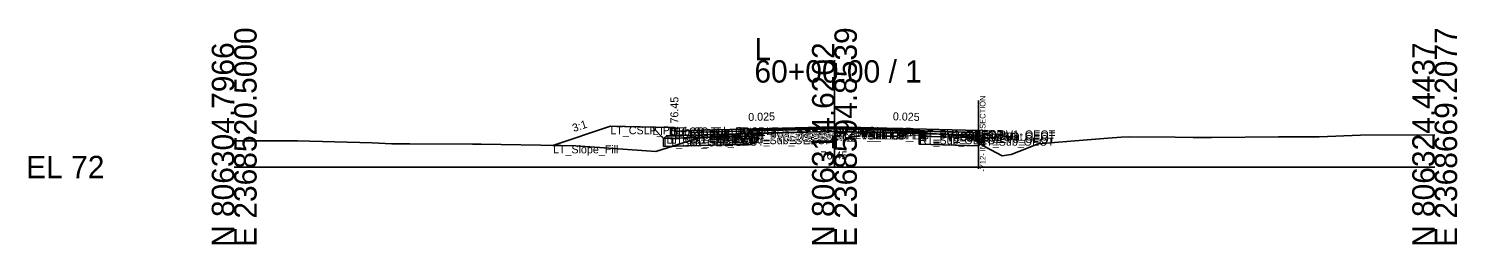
# Model space of a CAD drawing. Extents: x -26 to 8153, y -10 to 9520.
# Drawn here: x 4974.3 to 5152.8, y 8990.3 to 9017.3 of the extents above; entities that cross this region are included whole.
import ezdxf

# ---------------------------------------------------------------- set-up
doc = ezdxf.new("R2010")
doc.units = 0
for name, color, linetype in [('Exist CMT Pavement', 7, 'Continuous'), ('Exist Cross Section Cell', 7, 'Continuous'), ('Exist XS Center Line Elevation Label', 7, 'Continuous'), ('Exist XS Ground Line', 7, 'Continuous'), ('Prop CMT Conc Surface', 7, 'Continuous'), ('Prop CMT Concrete Structures', 7, 'Continuous'), ('Prop CMT Pvmt Course 1', 7, 'Continuous'), ('Prop CMT Pvmt Course 1 CG', 7, 'Continuous'), ('Prop CMT Pvmt Course 1 Wedge', 7, 'Continuous'), ('Prop CMT Pvmt Course 2', 7, 'Continuous'), ('Prop CMT Pvmt Course 2 Wedge', 7, 'Continuous'), ('Prop CMT Pvmt Course 3', 7, 'Continuous'), ('Prop CMT Pvmt Course 3 Wedge', 7, 'Continuous'), ('Prop CMT Pvmt Surface', 7, 'Continuous'), ('Prop CMT Pvmt Wedge Surface 1', 7, 'Continuous'), ('Prop CMT Pvmt Wedge Surface 2', 7, 'Continuous'), ('Prop CMT Pvmt Wedge Surface 3', 7, 'Continuous'), ('Prop CMT Shallow Undercut', 7, 'Continuous'), ('Prop CMT Shallow Undercut Boundary', 7, 'Continuous'), ('Prop CMT Shear Line', 7, 'Continuous'), ('Prop CMT Slope Grass', 7, 'Continuous'), ('Prop CMT Subgrade Earthwork', 7, 'Continuous'), ('Prop XS Earthwork Shape', 7, 'Continuous'), ('Prop XS Hydro Elevations', 7, 'Continuous'), ('Prop XS SE Text', 7, 'Continuous'), ('Prop XS Side Slope Text', 7, 'Continuous'), ('Prop XS Subgrade Earthwork', 7, 'Continuous'), ('Scratch_Level_2', 7, 'Continuous'), ('Scratch_Level_6', 7, 'Continuous')]:
    doc.layers.add(name, color=color, linetype=linetype)

msp = doc.modelspace()

# ---------------------------------------------------------------- linework, layer by layer
at = {"layer": 'Exist CMT Pavement'}
for p, q in [((5064.59, 9004.26), (5072.68, 9004.42)), ((5072.68, 9004.42), (5074.68, 9004.46)), ((5074.68, 9004.46), (5075, 9004.45)), ((5075, 9004.45), (5077.04, 9004.41)), ((5077.04, 9004.41), (5085.6, 9004.31))]:
    msp.add_line(p, q, dxfattribs=at)
at = {"layer": 'Exist Cross Section Cell'}
for p, q in [((5075, 9000), (5075, 9013.37)), ((5000, 9000), (5075, 9000)), ((5075, 9000), (5150, 9000))]:
    msp.add_line(p, q, dxfattribs=at)
at = {"layer": 'Exist XS Ground Line'}
for p, q in [((5052.7, 9001.93), (5057.94, 9003.63)), ((5057.94, 9003.63), (5062.69, 9004.08)), ((5062.69, 9004.08), (5064.59, 9004.26)), ((5064.59, 9004.26), (5072.68, 9004.42)), ((5072.68, 9004.42), (5074.68, 9004.46)), ((5074.68, 9004.46), (5075, 9004.45)), ((5075, 9004.45), (5077.04, 9004.41)), ((5077.04, 9004.41), (5085.6, 9004.31)), ((5085.6, 9004.31), (5087.26, 9004.18)), ((5087.26, 9004.18), (5091.74, 9003.84)), ((5091.74, 9003.84), (5093.83, 9002.54)), ((5104.53, 9003.25), (5109.15, 9003.61)), ((5109.15, 9003.61), (5110.81, 9003.75)), ((5110.81, 9003.75), (5111.86, 9003.79)), ((5111.86, 9003.79), (5117.57, 9003.73)), ((5117.57, 9003.73), (5119.84, 9003.69)), ((5119.84, 9003.69), (5122.13, 9003.69)), ((5122.13, 9003.69), (5130.48, 9003.77)), ((5130.48, 9003.77), (5135.56, 9003.79)), ((5135.56, 9003.79), (5140.73, 9003.98)), ((5140.73, 9003.98), (5150, 9004.04)), ((5000, 9003.26), (5002.86, 9003.29)), ((5002.86, 9003.29), (5007.9, 9003.26)), ((5007.9, 9003.26), (5017.22, 9003.01)), ((5017.22, 9003.01), (5019.68, 9002.92)), ((5019.68, 9002.92), (5021.94, 9002.91)), ((5021.94, 9002.91), (5029.77, 9002.86)), ((5029.77, 9002.86), (5030.85, 9002.86)), ((5030.85, 9002.86), (5040.83, 9002.69)), ((5040.83, 9002.69), (5042.69, 9002.65)), ((5042.69, 9002.65), (5052.7, 9001.93)), ((5093.83, 9002.54), (5095.94, 9001.42)), ((5097.1, 9001.59), (5098.04, 9001.96)), ((5098.04, 9001.96), (5100.46, 9002.9)), ((5100.46, 9002.9), (5104.53, 9003.25)), ((5095.94, 9001.42), (5096.8, 9001.52)), ((5096.8, 9001.52), (5097.1, 9001.59))]:
    msp.add_line(p, q, dxfattribs=at)
at = {"layer": 'Prop CMT Conc Surface'}
for points in [[(5055, 9004.45), (5055, 9004.95), (5054.5, 9004.95)], [(5057, 9004.58), (5055, 9004.45)]]:
    msp.add_lwpolyline(points, dxfattribs=at)
at = {"layer": 'Prop CMT Concrete Structures'}
for points in [[(5057, 9004.58), (5055, 9004.45), (5055, 9004.95), (5054.5, 9004.95)], [(5054.5, 9004.95), (5054.5, 9003.93), (5057, 9004)], [(5057, 9004), (5057, 9004.58)]]:
    msp.add_lwpolyline(points, dxfattribs=at)
at = {"layer": 'Prop CMT Pvmt Course 1'}
for points in [[(5075, 9005.03), (5057, 9004.58)], [(5057, 9004.58), (5057, 9004.33)], [(5057, 9004.33), (5064.59, 9004.52)], [(5064.59, 9004.64), (5075, 9004.91)], [(5064.59, 9004.52), (5064.59, 9004.64)], [(5075, 9004.78), (5075, 9005.03)], [(5075, 9005.03), (5093, 9004.58)], [(5075, 9004.78), (5075, 9005.03)], [(5075, 9004.91), (5075, 9004.78), (5075, 9004.78)], [(5085.6, 9004.64), (5075, 9004.91)], [(5075, 9004.91), (5075, 9004.78), (5075, 9004.78)], [(5085.6, 9004.51), (5085.6, 9004.64)], [(5093, 9004.33), (5085.6, 9004.51)], [(5093, 9004.58), (5093, 9004.33)]]:
    msp.add_lwpolyline(points, dxfattribs=at)
at = {"layer": 'Prop CMT Pvmt Course 1 CG'}
for points in [[(5057, 9004), (5054, 9003.92), (5053.66, 9003.58)], [(5053.66, 9003.58), (5057, 9003.67)], [(5057, 9003.67), (5057, 9004)]]:
    msp.add_lwpolyline(points, dxfattribs=at)
at = {"layer": 'Prop CMT Pvmt Course 1 Wedge'}
for points in [[(5075, 9004.91), (5064.59, 9004.64)], [(5075, 9004.91), (5085.6, 9004.64)]]:
    msp.add_lwpolyline(points, dxfattribs=at)
at = {"layer": 'Prop CMT Pvmt Course 2'}
for points in [[(5064.59, 9004.52), (5057, 9004.33)], [(5057, 9004.33), (5057, 9004)], [(5057, 9004), (5064.59, 9004.19)], [(5064.59, 9004.19), (5064.59, 9004.52)], [(5085.6, 9004.18), (5085.6, 9004.51)], [(5085.6, 9004.51), (5093, 9004.33)], [(5093, 9004), (5085.6, 9004.18)], [(5093, 9004.33), (5093, 9004)]]:
    msp.add_lwpolyline(points, dxfattribs=at)
at = {"layer": 'Prop CMT Pvmt Course 2 Wedge'}
for points in [[(5075, 9004.78), (5064.59, 9004.52)], [(5075, 9004.78), (5085.6, 9004.51)]]:
    msp.add_lwpolyline(points, dxfattribs=at)
at = {"layer": 'Prop CMT Pvmt Course 3'}
for points in [[(5064.59, 9004.19), (5057, 9004)], [(5057, 9004), (5057, 9003.67)], [(5057, 9003.67), (5064.59, 9003.86)], [(5064.59, 9003.86), (5064.59, 9004.19)], [(5085.6, 9004.18), (5093, 9004)], [(5085.6, 9003.85), (5085.6, 9004.18)], [(5093, 9003.67), (5085.6, 9003.85)], [(5093, 9004), (5093, 9003.67)]]:
    msp.add_lwpolyline(points, dxfattribs=at)
at = {"layer": 'Prop CMT Pvmt Course 3 Wedge'}
for points in [[(5075, 9004.45), (5064.59, 9004.19)], [(5075, 9004.45), (5085.6, 9004.18)]]:
    msp.add_lwpolyline(points, dxfattribs=at)
at = {"layer": 'Prop CMT Pvmt Surface'}
for points in [[(5075, 9005.03), (5057, 9004.58)], [(5075, 9005.03), (5093, 9004.58), (5093, 9003.67)]]:
    msp.add_lwpolyline(points, dxfattribs=at)
at = {"layer": 'Prop CMT Pvmt Wedge Surface 1'}
for points in [[(5057, 9004.33), (5057, 9004.58)], [(5064.59, 9004.52), (5057, 9004.33)], [(5075, 9004.91), (5064.59, 9004.64)], [(5064.59, 9004.64), (5064.59, 9004.52)], [(5075, 9004.91), (5085.6, 9004.64)], [(5085.6, 9004.64), (5085.6, 9004.51)], [(5085.6, 9004.51), (5093, 9004.33)], [(5093, 9004.33), (5093, 9004.58)]]:
    msp.add_lwpolyline(points, dxfattribs=at)
at = {"layer": 'Prop CMT Pvmt Wedge Surface 2'}
for points in [[(5075, 9004.78), (5057, 9004.33)], [(5057, 9004.33), (5057, 9004.58)], [(5075, 9004.78), (5093, 9004.33)], [(5093, 9004.33), (5093, 9004.58)]]:
    msp.add_lwpolyline(points, dxfattribs=at)
at = {"layer": 'Prop CMT Pvmt Wedge Surface 3'}
for points in [[(5057, 9004), (5057, 9004.58)], [(5075, 9004.45), (5057, 9004)], [(5075, 9004.45), (5093, 9004)], [(5093, 9004), (5093, 9004.58)]]:
    msp.add_lwpolyline(points, dxfattribs=at)
at = {"layer": 'Prop CMT Shallow Undercut'}
for points in [[(5064.59, 9003.86), (5064.59, 9002.86), (5054.79, 9002.61), (5057.94, 9003.63), (5058.76, 9003.71)], [(5093, 9003.06), (5093, 9002.67), (5085.6, 9002.85), (5085.6, 9003.85), (5091.97, 9003.69)]]:
    msp.add_lwpolyline(points, close=True, dxfattribs=at)
at = {"layer": 'Prop CMT Shallow Undercut Boundary'}
for p, q in [((5053.66, 9003.58), (5053.66, 9002.58)), ((5064.59, 9003.86), (5064.59, 9002.86)), ((5085.6, 9003.85), (5085.6, 9002.85)), ((5093, 9003.67), (5093, 9002.67)), ((5053.66, 9002.58), (5064.59, 9002.86)), ((5093, 9002.67), (5085.6, 9002.85))]:
    msp.add_line(p, q, dxfattribs=at)
at = {"layer": 'Prop CMT Shear Line'}
msp.add_line((5093, 8999.76), (5093, 9008.32), dxfattribs=at)
at = {"layer": 'Prop CMT Slope Grass'}
msp.add_lwpolyline([(5054.5, 9004.95), (5047, 9005.1), (5039.83, 9002.71)], dxfattribs=at)
at = {"layer": 'Prop CMT Subgrade Earthwork'}
for points in [[(5057, 9003.67), (5053.66, 9003.58), (5052.25, 9004.99)], [(5064.59, 9003.86), (5057, 9003.67)], [(5064.59, 9003.86), (5064.6, 9004.26)], [(5085.6, 9003.85), (5085.59, 9004.31)], [(5085.6, 9003.85), (5093, 9003.67)]]:
    msp.add_lwpolyline(points, dxfattribs=at)
at = {"layer": 'Prop XS Earthwork Shape'}
for points in [[(5040.83, 9002.69), (5042.69, 9002.65), (5052.7, 9001.93), (5054.79, 9002.61), (5053.66, 9002.58), (5053.66, 9003.58), (5052.25, 9004.99), (5047, 9005.1), (5039.83, 9002.71)], [(5058.76, 9003.71), (5057, 9003.67), (5053.66, 9003.58), (5053.66, 9002.58), (5054.79, 9002.61), (5057.94, 9003.63)], [(5064.59, 9003.86), (5058.76, 9003.71), (5057.94, 9003.63), (5054.79, 9002.61), (5064.59, 9002.86)], [(5064.59, 9003.86), (5064.6, 9004.26), (5064.59, 9004.26), (5062.69, 9004.08), (5058.76, 9003.71)], [(5085.6, 9004.31), (5087.26, 9004.18), (5091.74, 9003.84), (5091.97, 9003.69), (5085.6, 9003.85), (5085.59, 9004.31)], [(5093, 9002.67), (5085.6, 9002.85), (5085.6, 9003.85), (5091.97, 9003.69), (5093, 9003.06)], [(5091.97, 9003.69), (5093, 9003.06), (5093, 9003.67)]]:
    msp.add_lwpolyline(points, close=True, dxfattribs=at)
at = {"layer": 'Prop XS Subgrade Earthwork'}
for p, q in [((5053.66, 9003.58), (5064.59, 9003.86)), ((5085.6, 9003.85), (5093, 9003.67))]:
    msp.add_line(p, q, dxfattribs=at)
at = {"layer": 'Scratch_Level_6'}
for points in [[(5064.59, 9003.86), (5064.59, 9002.86), (5054.79, 9002.61), (5057.94, 9003.63), (5058.76, 9003.71)], [(5093, 9003.06), (5093, 9002.67), (5085.6, 9002.85), (5085.6, 9003.85), (5091.97, 9003.69)]]:
    msp.add_lwpolyline(points, close=True, dxfattribs=at)

# ---------------------------------------------------------------- texts
at = {"layer": 'Exist Cross Section Cell'}
for s, p in [('E 2368520.5000', (5002.8, 8990)), ('E 2368594.8539', (5077.8, 8990)), ('E 2368669.2077', (5152.8, 8990)), ('N 806304.7966', (5000, 8990)), ('N 806314.6202', (5075, 8990)), ('N 806324.4437', (5150, 8990))]:
    msp.add_text(s, height=2.8, rotation=90, dxfattribs=at).set_placement(p)
for s, p in [('L', (5065, 9013.37)), ('60+00.00 / 1', (5065, 9010.57)), ('EL 72', (4974, 8998.6))]:
    msp.add_text(s, height=2.8, dxfattribs=at).set_placement(p)
at = {"layer": 'Exist XS Center Line Elevation Label'}
msp.add_text('76.45', height=1, dxfattribs=at).set_placement((5073.27, 9000.95))
at = {"layer": 'Prop CMT Shear Line'}
msp.add_text('-Y12- INTERSECTION', height=0.7, rotation=90, dxfattribs=at).set_placement((5093.87, 8999.43))
at = {"layer": 'Prop XS Hydro Elevations'}
msp.add_text('76.45', height=1, rotation=90, dxfattribs=at).set_placement((5055.5, 9005.45))
at = {"layer": 'Prop XS SE Text'}
for rotation, p in [(1.4321, (5064.24, 9005.76)), (358.5679, (5082.29, 9005.85))]:
    msp.add_text('0.025', height=1, rotation=rotation, dxfattribs=at).set_placement(p)
at = {"layer": 'Prop XS Side Slope Text'}
msp.add_text('3:1', height=1, rotation=18.4349, dxfattribs=at).set_placement((5042.43, 9004.37))
at = {"layer": 'Scratch_Level_2'}
for s, p in [('LT_CSLP_Pnt', (5047, 9004.1)), ('LT_Sub_Trench_Out_DLT', (5052.25, 9003.99)), ('LT_Sub_OEOP', (5053.66, 9002.58)), ('LT_CG1_Shelf_Out', (5054, 9002.92)), ('LT_CG_Top_BOC', (5054.5, 9003.95)), ('LT_CG_Bot_BOC', (5054.5, 9002.93)), ('LT_CG_Top_Face', (5055, 9003.95)), ('LT_CG_Top_Gut', (5055, 9003.45)), ('LT_PV1_OEOT', (5057, 9003.58)), ('LT_PV2_OEOT', (5057, 9003.33)), ('LT_PV3_OEOT', (5057, 9003)), ('LT_CG_Bot_IE', (5057, 9003)), ('LT_Sub_OEOT', (5057, 9002.67)), ('LT_PV1_OEEOP', (5064.59, 9003.64)), ('LT_PV2_OEEOP', (5064.59, 9003.52)), ('LT_PV_OEEOP_EG', (5064.59, 9003.26)), ('LT_PV3_OEEOP', (5064.59, 9003.19)), ('LT_Sub_OEEOP', (5064.59, 9002.86)), ('LT_PV_Sub_Tie_Out', (5064.6, 9003.26)), ('PV1_PGL', (5075, 9004.03)), ('RT_PV1_IEEOP', (5075, 9003.91)), ('LT_PV1_IEEOP', (5075, 9003.91)), ('RT_PV2_IEEOP', (5075, 9003.78)), ('LT_PV2_IEEOP', (5075, 9003.78)), ('PV2_PGL', (5075, 9003.78)), ('RT_PV_IEEOP_EG', (5075, 9003.45)), ('LT_PV_IEEOP_EG', (5075, 9003.45)), ('RT_PV3_IEEOP', (5075, 9003.45)), ('LT_PV3_IEEOP', (5075, 9003.45)), ('RT_PV_Sub_Tie_Out', (5085.59, 9003.31)), ('RT_PV1_OEEOP', (5085.6, 9003.64)), ('RT_PV2_OEEOP', (5085.6, 9003.51)), ('RT_PV_OEEOP_EG', (5085.6, 9003.31)), ('RT_PV3_OEEOP', (5085.6, 9003.18)), ('RT_Sub_OEEOP', (5085.6, 9002.85)), ('RT_PV1_OEOT', (5093, 9003.58)), ('RT_PV2_OEOT', (5093, 9003.33)), ('RT_PV3_OEOT', (5093, 9003)), ('RT_Sub_OEOT', (5093, 9002.67)), ('LT_Slope_Fill', (5039.83, 9001.71))]:
    msp.add_text(s, height=1, dxfattribs=at).set_placement(p)

doc.saveas('drawing.dxf')
